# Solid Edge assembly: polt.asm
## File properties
Author: Mac
Template: Normal.asm
Last saved by: Mac
Revision: 6
Application: Solid Edge
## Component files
jala_polt.par
poldi_r6ngas.par
poldi_splint.par
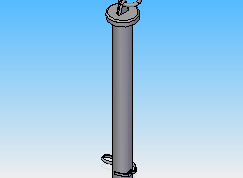
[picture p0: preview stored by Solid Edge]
